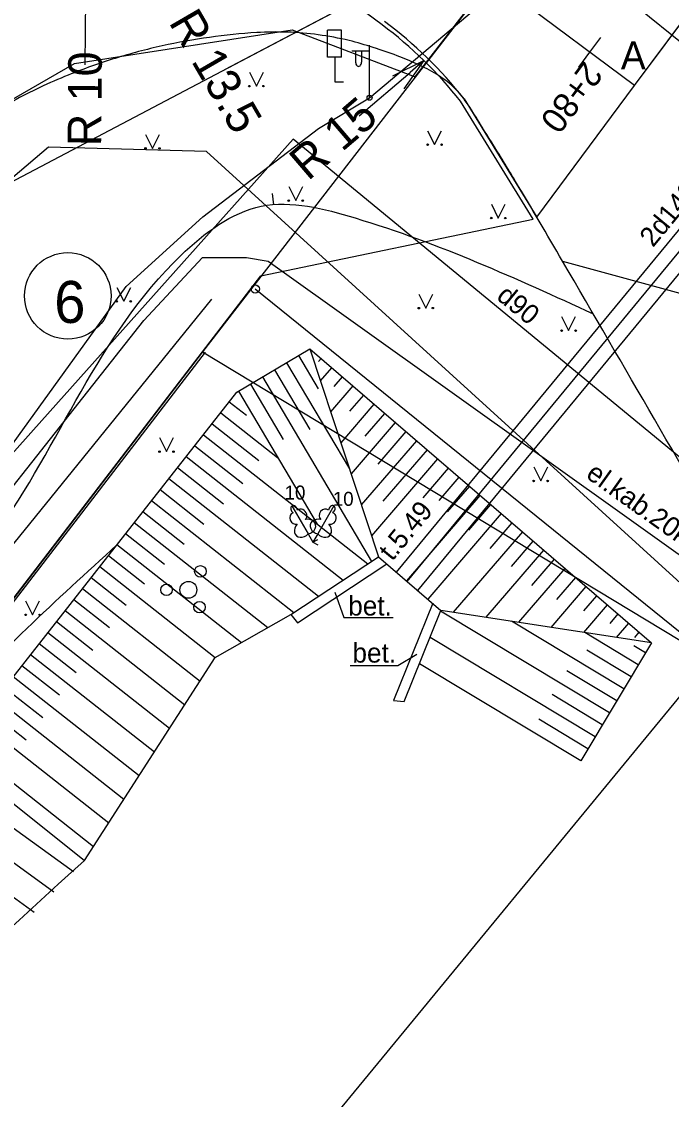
# Model space of a CAD drawing. Extents: x 514086 to 514457, y 297399 to 297567.
# Drawn here: x 514318.55 to 514341.8, y 297493.97 to 297532.52 of the extents above; entities that cross this region are included whole.
import ezdxf

# ---------------------------------------------------------------- set-up
doc = ezdxf.new("R2010")
doc.units = 0
for name, color, linetype in [('AA_Apzimejumi', 7, 'Continuous'), ('AA_Brauktuve', 7, 'Continuous'), ('AA_cela_mala', 7, 'Continuous'), ('AA_Ielas_ass', 7, 'Continuous'), ('AA_izmeri', 7, 'Continuous'), ('AA_Zale', 7, 'Continuous'), ('Level 1', 7, 'Continuous'), ('Level 14', 7, 'Continuous'), ('Level 16', 7, 'Continuous'), ('Level 17', 7, 'Continuous'), ('Level 18', 7, 'Continuous'), ('Level 23', 7, 'Continuous'), ('Level 29', 7, 'Continuous'), ('Level 31', 7, 'Continuous'), ('Level 32', 7, 'Continuous'), ('Level 35', 7, 'Continuous'), ('Level 36', 7, 'Continuous'), ('Level 37', 7, 'Continuous'), ('Level 41', 7, 'Continuous'), ('Level 42', 7, 'Continuous'), ('Level 44', 7, 'Continuous'), ('Level 45', 7, 'Continuous'), ('Level 46', 7, 'Continuous'), ('Level 61', 7, 'Continuous'), ('Level 7', 7, 'Continuous'), ('Level 8', 7, 'Continuous'), ('Level 9', 7, 'Continuous')]:
    doc.layers.add(name, color=color, linetype=linetype)

msp = doc.modelspace()

# ---------------------------------------------------------------- linework, layer by layer
at = {"layer": 'AA_Apzimejumi'}
msp.add_circle((514320.207, 297522.708), 1.546, dxfattribs=at)
at = {"layer": 'AA_Brauktuve'}
for p, q in [((514340.48, 297530.225), (514346.364, 297538.131)), ((514336.981, 297525.523), (514340.48, 297530.225))]:
    msp.add_line(p, q, dxfattribs=at)
msp.add_lwpolyline([(514334.38, 297529.75), (514336.981, 297525.523), (514340.48, 297530.225), (514346.364, 297538.131)], dxfattribs=at)
msp.add_arc((514322.584, 297520.483), 15, 38.1536, 53.3424, dxfattribs=at)
at = {"layer": 'AA_cela_mala'}
for p, q in [((514331.45, 297532.396), (514328.281, 297534.754)), ((514336.853, 297525.444), (514334.256, 297529.664)), ((514334.38, 297529.75), (514336.981, 297525.523))]:
    msp.add_line(p, q, dxfattribs=at)
for radius, start in [(14.85, 38.1866), (15, 38.1536)]:
    msp.add_arc((514322.584, 297520.483), radius, start, 53.3424, dxfattribs=at)
at = {"layer": 'AA_Ielas_ass'}
for p, q in [((514340.48, 297530.225), (514330.885, 297537.367)), ((514338.876, 297531.419), (514339.27, 297531.949)), ((514338.482, 297530.89), (514338.876, 297531.419))]:
    msp.add_line(p, q, dxfattribs=at)
at = {"layer": 'AA_izmeri'}
for p, q in [((514320.829, 297530.966), (514320.848, 297533.365)), ((514332.944, 297531.123), (514332.449, 297530.699)), ((514330.626, 297529.139), (514332.449, 297530.699))]:
    msp.add_line(p, q, dxfattribs=at)
msp.add_lwpolyline([(514331.837, 297530.57), (514332.944, 297531.123), (514332.227, 297530.114)], dxfattribs=at)
at = {"layer": 'AA_Zale'}
for p, q in [((514327.112, 297523.423), (514336.853, 297525.444)), ((514325.029, 297520.708), (514327.112, 297523.423)), ((514283.198, 297466.177), (514325.029, 297520.708))]:
    msp.add_line(p, q, dxfattribs=at)
for points in [[(514331.45, 297532.396), (514328.281, 297534.754)], [(514236.652, 297413.496), (514237.314, 297412.963), (514250.581, 297429.476), (514253.4, 297427.333), (514283.198, 297466.177), (514325.029, 297520.708), (514327.112, 297523.423), (514336.853, 297525.444), (514334.256, 297529.664)]]:
    msp.add_lwpolyline(points, dxfattribs=at)
msp.add_arc((514322.584, 297520.483), 14.85, 38.1866, 53.3424, dxfattribs=at)
at = {"layer": 'Level 1'}
for p, q in [((514328.802, 297514.201), (514328.975, 297513.9)), ((514329.148, 297514.201), (514328.975, 297513.9)), ((514328.975, 297513.9), (514329.148, 297514)), ((514328.975, 297513.9), (514329.148, 297513.8))]:
    msp.add_line(p, q, dxfattribs=at)
for points in [[(514325.349, 297522.592), (514313.48, 297507.964), (514284.691, 297471.315), (514272.976, 297455.563)], [(514328.225, 297515.199), (514328.802, 297514.201)], [(514328.419, 297515.043), (514328.417, 297515.043)], [(514329.725, 297515.199), (514329.148, 297514.201)], [(514329.686, 297514.953), (514329.686, 297514.954)]]:
    msp.add_lwpolyline(points, dxfattribs=at)
for centre, radius in [((514324.947, 297512.855), 0.207), ((514323.736, 297512.195), 0.204), ((514324.52, 297512.195), 0.301), ((514324.915, 297511.575), 0.205)]:
    msp.add_circle(centre, radius, dxfattribs=at)
for centre, major_axis, ratio, start_param, end_param in [((514328.3, 297515.069), (0.075, -0.13), 0.707107, 3.14537, 5.287485), ((514328.3, 297515.069), (0.075, -0.13), 0.707107, 0.995701, 3.137816), ((514328.559, 297514.878), (0.14, -0.165), 0.861323, 0, 3.141593), ((514329.391, 297514.878), (-0.14, -0.165), 0.861323, 3.141593, 6.283185), ((514329.65, 297515.069), (-0.075, -0.13), 0.707107, 3.14537, 5.287485), ((514329.65, 297515.069), (-0.075, -0.13), 0.707107, 0.995701, 3.137816), ((514328.336, 297514.75), (0.073, -0.203), 0.861323, 3.141593, 6.283185), ((514328.756, 297514.458), (-0.313, -0.071), 0.814445, 1.531171, 4.712389), ((514329.194, 297514.458), (0.313, -0.071), 0.814445, 1.570796, 4.752015), ((514329.614, 297514.75), (-0.073, -0.203), 0.861323, 0, 3.141593), ((514328.601, 297514.369), (0.218, 0.236), 0.814445, 1.570796, 4.752015), ((514329.349, 297514.369), (-0.218, 0.236), 0.814445, 1.531171, 4.712389)]:
    msp.add_ellipse(centre, major_axis=major_axis, ratio=ratio, start_param=start_param, end_param=end_param, dxfattribs=at)
at = {"layer": 'Level 14'}
msp.add_circle((514326.909, 297522.954), 0.148, dxfattribs=at)
at = {"layer": 'Level 16'}
for p, q in [((514329.999, 297532.208), (514329.499, 297532.208)), ((514329.499, 297531.239), (514329.499, 297532.208)), ((514329.999, 297531.239), (514329.999, 297532.208)), ((514329.999, 297531.239), (514329.499, 297531.239)), ((514329.753, 297531.239), (514329.753, 297530.361)), ((514329.753, 297530.361), (514330.068, 297530.361))]:
    msp.add_line(p, q, dxfattribs=at)
at = {"layer": 'Level 17'}
for points in [[(514282.572, 297503.806), (514288.467, 297511.508), (514295.326, 297506.485), (514302.185, 297501.461), (514317.671, 297526.51), (514327.071, 297531.454), (514337.273, 297536.82), (514349.958, 297543.491), (514353.979, 297547.673)], [(514341.745, 297539.172), (514325.814, 297530.793)]]:
    msp.add_lwpolyline(points, dxfattribs=at)
at = {"layer": 'Level 18'}
msp.add_line((514331, 297529.794), (514353.114, 297548.412), dxfattribs=at)
at = {"layer": 'Level 23'}
for p, q in [((514326.703, 297530.707), (514326.953, 297530.207)), ((514326.953, 297530.207), (514327.203, 297530.707)), ((514333.075, 297528.614), (514333.325, 297528.114)), ((514333.325, 297528.114), (514333.575, 297528.614)), ((514322.986, 297528.481), (514323.236, 297527.981)), ((514323.236, 297527.981), (514323.486, 297528.481)), ((514328.109, 297526.613), (514328.359, 297526.113)), ((514328.359, 297526.113), (514328.609, 297526.613)), ((514335.355, 297525.988), (514335.605, 297525.488)), ((514335.605, 297525.488), (514335.855, 297525.988)), ((514321.956, 297523.012), (514322.206, 297522.512)), ((514322.206, 297522.512), (514322.456, 297523.012)), ((514332.762, 297522.77), (514333.012, 297522.27)), ((514333.012, 297522.27), (514333.262, 297522.77)), ((514337.869, 297521.965), (514338.119, 297521.465)), ((514338.119, 297521.465), (514338.369, 297521.965)), ((514323.486, 297517.637), (514323.736, 297517.137)), ((514323.736, 297517.137), (514323.986, 297517.637)), ((514336.87, 297516.59), (514337.12, 297516.09)), ((514337.12, 297516.09), (514337.37, 297516.59)), ((514318.699, 297511.8), (514318.949, 297511.3)), ((514318.949, 297511.3), (514319.199, 297511.8))]:
    msp.add_line(p, q, dxfattribs=at)
for centre, radius in [((514326.703, 297530.207), 0.028), ((514327.203, 297530.207), 0.0263), ((514333.074, 297528.113), 0.028), ((514333.574, 297528.113), 0.0263), ((514322.986, 297527.98), 0.028), ((514323.486, 297527.98), 0.0263), ((514328.108, 297526.113), 0.028), ((514328.608, 297526.113), 0.0263), ((514335.354, 297525.488), 0.028), ((514335.854, 297525.488), 0.0263), ((514321.955, 297522.511), 0.028), ((514322.455, 297522.511), 0.0263), ((514332.762, 297522.269), 0.028), ((514333.262, 297522.269), 0.0263), ((514337.869, 297521.464), 0.028), ((514338.369, 297521.464), 0.0263), ((514323.486, 297517.136), 0.028), ((514323.986, 297517.136), 0.0263), ((514336.869, 297516.089), 0.028), ((514337.369, 297516.089), 0.0263), ((514318.699, 297511.3), 0.028), ((514319.199, 297511.3), 0.0263)]:
    msp.add_circle(centre, radius, dxfattribs=at)
at = {"layer": 'Level 29'}
for p, q in [((514341.642, 297542.18), (514325.029, 297520.708)), ((514325.029, 297520.708), (514241.366, 297411.646)), ((514325.029, 297520.708), (514343.202, 297509.728)), ((514291.267, 297446.65), (514343.202, 297509.728))]:
    msp.add_line(p, q, dxfattribs=at)
at = {"layer": 'Level 31'}
for p, q in [((514315.568, 297505.621), (514320.414, 297502.121)), ((514314.982, 297504.811), (514319.708, 297501.397)), ((514314.397, 297504), (514319.001, 297500.674))]:
    msp.add_line(p, q, dxfattribs=at)
at = {"layer": 'Level 32'}
msp.add_line((514327.578, 297525.967), (514327.525, 297526.363), dxfattribs=at)
msp.add_spline([(514321.954, 297513.799), (514315.665, 297507.71), (514304.919, 297493.222), (514302.22, 297489.529), (514296.552, 297484.063), (514293.92, 297480.636), (514293.775, 297479.526), (514293.484, 297478.389), (514290.105, 297476.03), (514288.603, 297473.324), (514288.233, 297471.034), (514286.104, 297469.237), (514283.964, 297468.854), (514283.423, 297470.519), (514284.598, 297472.872), (514289.498, 297479.331), (514295.836, 297489.424), (514303.534, 297495.399), (514308.484, 297502.218), (514312.919, 297508.652), (514317.614, 297514.163), (514324.249, 297524.153), (514327.127, 297525.911), (514330.479, 297525.495), (514338.994, 297522.069)], degree=3, dxfattribs=at)
at = {"layer": 'Level 35'}
msp.add_line((514325.114, 297520.693), (514303.579, 297492.661), dxfattribs=at)
at = {"layer": 'Level 36'}
msp.add_spline([(514320.804, 297502.52), (514306.724, 297488.103), (514301.133, 297479.973), (514270.315, 297441.123), (514246.087, 297412.115), (514239.566, 297403.275)], degree=3, dxfattribs=at)
at = {"layer": 'Level 37'}
msp.add_lwpolyline([(514337.902, 297523.95), (514347.086, 297521.446), (514349.822, 297524.212)], dxfattribs=at)
for points in [[(514331.99, 297531.295), (514330.267, 297531.837), (514329.163, 297532.042), (514328.062, 297532.137), (514326.965, 297532.121), (514325.273, 297531.948), (514323.584, 297531.645), (514321.899, 297531.2), (514320.221, 297530.603), (514319.204, 297530.159), (514318.247, 297529.666), (514317.331, 297529.108), (514316.44, 297528.469), (514315.34, 297527.522), (514314.336, 297526.506), (514313.382, 297525.454), (514312.429, 297524.398), (514303.497, 297508.608)], [(514344.469, 297512.634), (514337.902, 297523.95), (514336.222, 297526.8), (514335.357, 297528.214), (514334.916, 297528.919), (514334.467, 297529.623), (514333.988, 297530.187), (514333.391, 297530.632), (514332.713, 297530.99), (514331.99, 297531.295)]]:
    msp.add_spline(points, degree=3, dxfattribs=at)
at = {"layer": 'Level 41'}
for p, q in [((514328.858, 297520.81), (514331.317, 297513.375)), ((514328.457, 297520.573), (514329.165, 297519.377)), ((514329.263, 297520.462), (514329.177, 297520.362)), ((514327.597, 297520.063), (514328.86, 297517.93)), ((514328.027, 297520.318), (514330.277, 297516.521)), ((514329.642, 297520.136), (514329.237, 297519.664)), ((514327.167, 297519.808), (514331.073, 297513.214)), ((514330.021, 297519.81), (514329.724, 297519.463)), ((514326.306, 297519.298), (514329.122, 297514.545)), ((514326.737, 297519.553), (514327.912, 297517.569)), ((514330.4, 297519.484), (514329.603, 297518.557)), ((514325.983, 297518.922), (514326.6, 297518.436)), ((514330.779, 297519.157), (514330.287, 297518.585)), ((514325.674, 297518.529), (514327.711, 297516.927)), ((514331.158, 297518.831), (514329.969, 297517.449)), ((514331.537, 297518.505), (514330.832, 297517.685)), ((514325.365, 297518.136), (514327.037, 297516.821)), ((514331.917, 297518.179), (514330.336, 297516.341)), ((514325.056, 297517.743), (514330.933, 297513.122)), ((514332.296, 297517.853), (514331.298, 297516.693)), ((514324.747, 297517.35), (514326.47, 297515.994)), ((514332.675, 297517.527), (514330.702, 297515.234)), ((514324.438, 297516.957), (514330.052, 297512.542)), ((514333.054, 297517.201), (514331.479, 297515.37)), ((514324.128, 297516.564), (514325.773, 297515.27)), ((514333.433, 297516.875), (514331.068, 297514.126)), ((514323.819, 297516.171), (514329.171, 297511.963)), ((514333.812, 297516.549), (514332.901, 297515.49)), ((514334.191, 297516.223), (514333.475, 297515.39)), ((514334.57, 297515.897), (514333.781, 297514.98)), ((514323.51, 297515.778), (514325.076, 297514.546)), ((514334.949, 297515.571), (514332.321, 297512.515)), ((514323.201, 297515.384), (514328.29, 297511.383)), ((514335.328, 297515.245), (514334.54, 297514.329)), ((514322.892, 297514.991), (514324.373, 297513.827)), ((514335.707, 297514.919), (514333.081, 297511.865)), ((514322.583, 297514.598), (514327.359, 297510.843)), ((514336.465, 297514.267), (514333.993, 297511.393)), ((514336.086, 297514.593), (514335.299, 297513.677)), ((514322.274, 297514.205), (514323.659, 297513.117)), ((514336.845, 297513.941), (514336.065, 297513.034)), ((514321.965, 297513.812), (514326.421, 297510.309)), ((514337.224, 297513.615), (514335.158, 297511.213)), ((514321.656, 297513.419), (514322.945, 297512.406)), ((514337.603, 297513.289), (514336.794, 297512.349)), ((514321.347, 297513.026), (514325.482, 297509.774)), ((514337.982, 297512.963), (514336.322, 297511.033)), ((514321.038, 297512.633), (514322.289, 297511.649)), ((514338.361, 297512.637), (514337.685, 297511.85)), ((514320.729, 297512.24), (514324.936, 297508.932)), ((514338.74, 297512.311), (514337.486, 297510.853)), ((514339.119, 297511.985), (514338.65, 297511.439)), ((514320.42, 297511.847), (514321.693, 297510.846)), ((514339.498, 297511.659), (514338.65, 297510.673)), ((514320.111, 297511.454), (514324.392, 297508.087)), ((514339.582, 297507.801), (514333.54, 297511.429)), ((514341.081, 297510.297), (514333.553, 297511.461)), ((514339.877, 297511.332), (514339.588, 297510.996)), ((514319.802, 297511.061), (514321.097, 297510.042)), ((514340.097, 297508.658), (514336.08, 297511.07)), ((514340.256, 297511.006), (514339.814, 297510.493)), ((514319.493, 297510.668), (514323.848, 297507.243)), ((514339.067, 297506.943), (514333.162, 297510.49)), ((514340.611, 297509.515), (514338.695, 297510.666)), ((514340.635, 297510.68), (514340.47, 297510.489)), ((514319.184, 297510.275), (514320.501, 297509.239)), ((514340.354, 297509.086), (514338.776, 297510.034)), ((514340.869, 297509.944), (514340.454, 297510.193)), ((514318.875, 297509.882), (514323.304, 297506.399)), ((514318.565, 297509.489), (514319.905, 297508.435)), ((514338.552, 297506.086), (514332.784, 297509.55)), ((514339.839, 297508.229), (514338.052, 297509.302)), ((514318.256, 297509.096), (514322.76, 297505.555)), ((514317.947, 297508.703), (514319.309, 297507.632)), ((514317.638, 297508.31), (514322.216, 297504.71)), ((514339.324, 297507.372), (514337.532, 297508.448)), ((514317.329, 297507.917), (514318.714, 297506.828)), ((514317.02, 297507.524), (514321.672, 297503.866)), ((514338.809, 297506.515), (514337.059, 297507.566)), ((514316.402, 297506.738), (514321.127, 297503.022)), ((514316.058, 297506.3), (514320.804, 297502.52))]:
    msp.add_line(p, q, dxfattribs=at)
for points in [[(514316.058, 297506.3), (514321.156, 297512.784), (514326.255, 297519.268), (514328.858, 297520.81), (514341.081, 297510.297), (514338.552, 297506.086)], [(514320.804, 297502.52), (514325.478, 297509.772), (514328.187, 297511.315)]]:
    msp.add_lwpolyline(points, dxfattribs=at)
at = {"layer": 'Level 42'}
for p, q in [((514326.909, 297522.954), (514342.416, 297510.433)), ((514328.187, 297511.315), (514331.317, 297513.375)), ((514332.243, 297508.206), (514333.553, 297511.461))]:
    msp.add_line(p, q, dxfattribs=at)
for points in [[(514328.187, 297511.315), (514328.416, 297511.019), (514331.612, 297513.122)], [(514331.317, 297513.375), (514333.553, 297511.461)], [(514329.752, 297512.107), (514330.082, 297511.205), (514331.848, 297511.205)], [(514333.257, 297511.714), (514331.856, 297508.233), (514332.243, 297508.206)], [(514330.303, 297509.491), (514332.005, 297509.491), (514332.686, 297509.891)]]:
    msp.add_lwpolyline(points, dxfattribs=at)
at = {"layer": 'Level 44'}
for p, q in [((514331, 297529.794), (514331, 297531.677)), ((514331, 297531.457), (514330.365, 297531.457)), ((514330.5, 297531.457), (514330.5, 297531.065)), ((514330.71, 297531.457), (514330.71, 297531.065))]:
    msp.add_line(p, q, dxfattribs=at)
msp.add_circle((514331, 297529.794), 0.09, dxfattribs=at)
msp.add_ellipse((514330.605, 297531.065), major_axis=(0, 0.151), ratio=0.695971, start_param=1.570796, end_param=4.712389, dxfattribs=at)
at = {"layer": 'Level 45'}
msp.add_lwpolyline([(514316.579, 297515.144), (514322.29, 297523.047), (514325.034, 297525.537), (514329.174, 297528.694), (514331, 297529.794)], dxfattribs=at)
at = {"layer": 'Level 46'}
msp.add_lwpolyline([(514139.134, 297486.37), (514229.261, 297420.493), (514237.863, 297414.208), (514250.009, 297428.181), (514295.433, 297494.723), (514312.775, 297524.542), (514316.491, 297528.738), (514320.446, 297531.016), (514328.236, 297532.215), (514332.539, 297530.572), (514332.631, 297530.536), (514341.642, 297542.18), (514320.211, 297553.997), (514285.885, 297496.27), (514243.195, 297433.696), (514241.534, 297432.407), (514239.451, 297432.203), (514209.969, 297445.237), (514194.45, 297457.413), (514175.859, 297473.677), (514139.316, 297503.122), (514133.046, 297508.174), (514130.604, 297489.221)], close=True, dxfattribs=at)
at = {"layer": 'Level 61'}
msp.add_lwpolyline([(514228.605, 297413.892), (514229.168, 297414.699), (514234.462, 297409.66), (514239.192, 297415.557), (514243.591, 297423.09), (514250.856, 297428.146), (514250.871, 297429.329), (514257.62, 297437.772), (514268.028, 297450.791), (514271.687, 297455.368), (514283.043, 297472.127), (514296.63, 297489.788), (514299.744, 297491.72), (514308.223, 297503.049), (514310.505, 297506.097), (514314.057, 297510.598), (514322.921, 297521.831), (514325.028, 297524.077), (514326.601, 297524.074), (514327.377, 297523.947), (514343.661, 297512.323), (514343.876, 297512.066)], dxfattribs=at)
at = {"layer": 'Level 7'}
msp.add_lwpolyline([(514343.326, 297511.34), (514325.164, 297527.868), (514319.52, 297528.02), (514310.019, 297519.951), (514298.017, 297529.861)], dxfattribs=at)
at = {"layer": 'Level 8'}
msp.add_lwpolyline([(514363.513, 297540.75), (514360.351, 297536.898), (514359.482, 297535.839), (514353.406, 297525.223), (514345.234, 297514.353), (514328.27, 297528.306), (514319.28, 297518.25), (514313.196, 297511.446), (514309.505, 297507.318), (514306.815, 297503.948), (514300.399, 297495.913), (514297.136, 297491.825), (514286.021, 297501.175)], dxfattribs=at)
at = {"layer": 'Level 9'}
for p, q in [((514314.507, 297554.105), (514350.919, 297524.681)), ((514331.962, 297512.822), (514358.315, 297544.772)), ((514332.722, 297512.172), (514359.087, 297544.135))]:
    msp.add_line(p, q, dxfattribs=at)
msp.add_lwpolyline([(514332.342, 297512.497), (514352.111, 297536.464), (514356.552, 297541.849), (514358.701, 297544.454)], dxfattribs=at)

# ---------------------------------------------------------------- texts
at = {"layer": 'AA_Apzimejumi'}
msp.add_text('6', height=1.5, dxfattribs=at).set_placement((514319.721, 297521.739))
at = {"layer": 'AA_Ielas_ass'}
msp.add_text('2+80', height=0.9, rotation=233.3425, dxfattribs=at).set_placement((514338.679, 297531.155))
at = {"layer": 'AA_izmeri'}
for s, rotation, p in [('R 13.5', 300.1644, (514323.797, 297532.494)), ('R 10', 89.5421, (514321.398, 297528.054)), ('R 15', 40.5584, (514328.795, 297526.793))]:
    msp.add_text(s, height=1.2, rotation=rotation, dxfattribs=at).set_placement(p)
at = {"layer": 'Level 1'}
for p in [(514327.775, 297515.424), (514329.5, 297515.199)]:
    msp.add_text(' 10', height=0.5, dxfattribs=at).set_placement(p)
at = {"layer": 'Level 37'}
msp.add_text('A', height=1, dxfattribs=at).set_placement((514339.986, 297530.806))
at = {"layer": 'Level 42'}
for p in [(514330.236, 297511.276), (514330.387, 297509.593)]:
    msp.add_text('bet.', height=0.7, dxfattribs=at).set_placement(p)
at = {"layer": 'Level 61'}
msp.add_text('el.kab.20kV', height=0.7, rotation=324.4799, dxfattribs=at).set_placement((514338.699, 297516.233))
at = {"layer": 'Level 8'}
msp.add_text('d90', height=0.7, rotation=320.5625, dxfattribs=at).set_placement((514335.502, 297522.621))
at = {"layer": 'Level 9'}
for s, p in [('2d1400', (514341.137, 297524.416)), ('t.5.49', (514331.809, 297513.195))]:
    msp.add_text(s, height=0.7, rotation=50.483, dxfattribs=at).set_placement(p)

doc.saveas('drawing.dxf')
